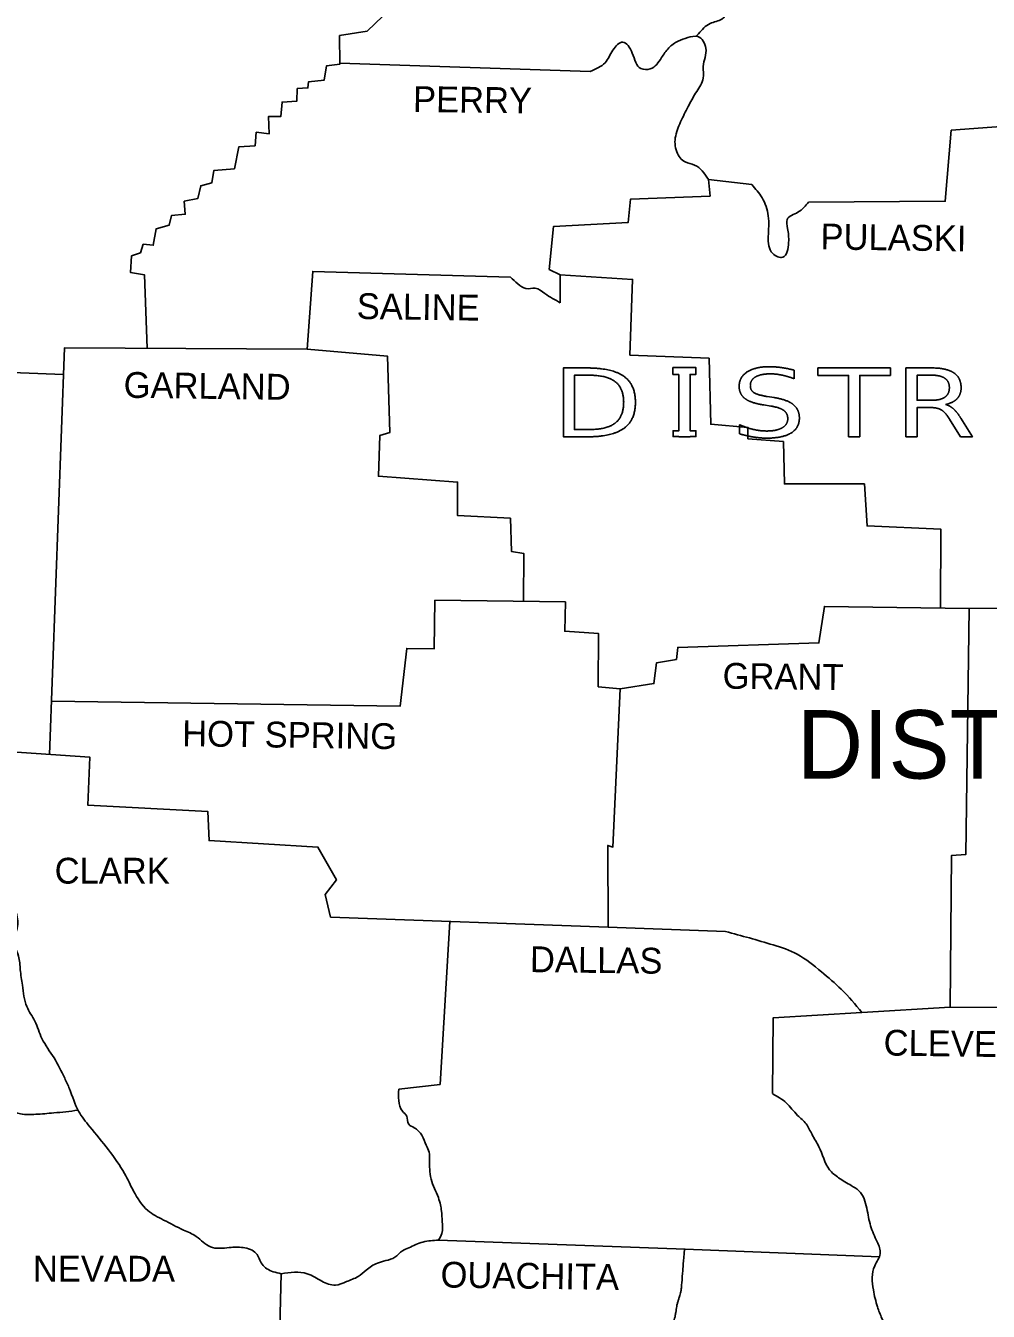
# Model space of a CAD drawing. Extents: x -0.54 to 1.64, y 0 to 0.92.
# Drawn here: x 1.1608 to 1.2333, y 0.624 to 0.7208 of the extents above; entities that cross this region are included whole.
import ezdxf

# ---------------------------------------------------------------- set-up
doc = ezdxf.new("R2010")
doc.units = 0
doc.layers.add('SHET_Annotations', color=7, linetype='Continuous')

msp = doc.modelspace()

# ---------------------------------------------------------------- linework, layer by layer
at = {"layer": 'SHET_Annotations'}
for p, q in [((1.211498, 0.720198), (1.211339, 0.720025)), ((1.218711, 0.694864), (1.218711, 0.694217)), ((1.216668, 0.692885), (1.217199, 0.692797)), ((1.216951, 0.692161), (1.216415, 0.692245)), ((1.230114, 0.69228), (1.230114, 0.69228)), ((1.214594, 0.69007), (1.214594, 0.690756))]:
    msp.add_line(p, q, dxfattribs=at)
for points in [[(1.233618, 0.817918), (1.233724, 0.806793), (1.232972, 0.806741), (1.233076, 0.795382), (1.229912, 0.794915), (1.230171, 0.79188), (1.23126, 0.790454), (1.231182, 0.786849), (1.224984, 0.786616), (1.224751, 0.781066), (1.219097, 0.780884), (1.218786, 0.77409), (1.219123, 0.773571), (1.219279, 0.762782), (1.229004, 0.762134), (1.228874, 0.738093), (1.236655, 0.737885), (1.236655, 0.713404), (1.230534, 0.712937), (1.230093, 0.707594), (1.219797, 0.707517)], [(1.188313, 0.722092), (1.18655, 0.720406), (1.184475, 0.720069), (1.184501, 0.717916), (1.183489, 0.717786), (1.183308, 0.716697), (1.182141, 0.716593), (1.182089, 0.716127), (1.181285, 0.716075), (1.181259, 0.715115), (1.180144, 0.715063), (1.180066, 0.713974), (1.179133, 0.713974), (1.179184, 0.712677), (1.178199, 0.712781), (1.178121, 0.71177), (1.176902, 0.711692), (1.176565, 0.710032), (1.175009, 0.709902), (1.174853, 0.708969), (1.174023, 0.708761), (1.173816, 0.707802), (1.172779, 0.707594), (1.172856, 0.706609), (1.171819, 0.706505), (1.171638, 0.705779), (1.170678, 0.70552), (1.170445, 0.704275), (1.169692, 0.704353), (1.169485, 0.703704), (1.168811, 0.703471), (1.168733, 0.702226), (1.169796, 0.702044), (1.169986, 0.696511)], [(1.203355, 0.717372), (1.1845, 0.717996)], [(1.215518, 0.708839), (1.21225, 0.709228), (1.21238, 0.707983), (1.206389, 0.70775), (1.206208, 0.705986), (1.20058, 0.705675), (1.200269, 0.702459), (1.201099, 0.702044), (1.201099, 0.699944)], [(1.197338, 0.701863), (1.182452, 0.702304), (1.182037, 0.696443), (1.163754, 0.696546), (1.16263, 0.665925)], [(1.201099, 0.702039), (1.206545, 0.701707), (1.206337, 0.696002), (1.212302, 0.695768), (1.212432, 0.690789), (1.215233, 0.690556), (1.215233, 0.6897), (1.217904, 0.689492), (1.217982, 0.686302), (1.223999, 0.686302), (1.224206, 0.683138), (1.229756, 0.682879), (1.22973, 0.676945)], [(1.182037, 0.696443), (1.18808, 0.695924), (1.188261, 0.690167), (1.187509, 0.689933), (1.187406, 0.686873), (1.19337, 0.686432), (1.19337, 0.683916), (1.197338, 0.683709), (1.197416, 0.681219), (1.19835, 0.681064), (1.198322, 0.677449)], [(1.145522, 0.69525), (1.16368, 0.694539)], [(1.203118, 0.695032), (1.201332, 0.695032), (1.201332, 0.689846), (1.203118, 0.689846)], [(1.203253, 0.690392), (1.202168, 0.690392), (1.202168, 0.694486), (1.203253, 0.694486)], [(1.22909, 0.695032), (1.227125, 0.695032), (1.227125, 0.689846), (1.227961, 0.689846), (1.227961, 0.692053), (1.228942, 0.692053)], [(1.22909, 0.692598), (1.227961, 0.692598), (1.227961, 0.694486), (1.22909, 0.694486)], [(1.23041, 0.691175), (1.231238, 0.689846), (1.232131, 0.689846), (1.231259, 0.691248)], [(1.284166, 0.682179), (1.266894, 0.682672), (1.26679, 0.677044), (1.231883, 0.676914)], [(1.162777, 0.66994), (1.189039, 0.669549), (1.189532, 0.673906), (1.191607, 0.67388), (1.191659, 0.677537), (1.201488, 0.677407), (1.201436, 0.675202), (1.203977, 0.675021), (1.203952, 0.671027), (1.205611, 0.670871)], [(1.205611, 0.670871), (1.208153, 0.67126), (1.208334, 0.672817), (1.209839, 0.673076), (1.209942, 0.673984), (1.220575, 0.674321), (1.22099, 0.67707), (1.231883, 0.676914)], [(1.231883, 0.676914), (1.231649, 0.658397), (1.23056, 0.658319), (1.230456, 0.646882)], [(1.205611, 0.670871), (1.205067, 0.658942), (1.204678, 0.659071), (1.204703, 0.652912)], [(1.157581, 0.657723), (1.157452, 0.660238), (1.158204, 0.66029), (1.15867, 0.666203), (1.165673, 0.665711), (1.165517, 0.662106), (1.174568, 0.661613), (1.174646, 0.659434), (1.182841, 0.658942), (1.184242, 0.656478), (1.183386, 0.655363), (1.183801, 0.653677), (1.204703, 0.652912)], [(1.192781, 0.653348), (1.192048, 0.641073), (1.188936, 0.64071)], [(1.204703, 0.652912), (1.213547, 0.652588)], [(1.230456, 0.646882), (1.223818, 0.646482)], [(1.230456, 0.646882), (1.246689, 0.646804)], [(1.223818, 0.646482), (1.217126, 0.646078), (1.217074, 0.640373)], [(1.191936, 0.629339), (1.210513, 0.628651), (1.225143, 0.628081)], [(1.180092, 0.626809), (1.179496, 0.60378), (1.173349, 0.604221), (1.173297, 0.602535), (1.165188, 0.603003)]]:
    msp.add_lwpolyline(points, dxfattribs=at)
for points in [[(1.210037, 0.694542), (1.209575, 0.694542), (1.209575, 0.69506), (1.211309, 0.69506), (1.211309, 0.694542), (1.210873, 0.694542), (1.210873, 0.690297), (1.211309, 0.690297), (1.211309, 0.68986), (1.210873, 0.68986), (1.210873, 0.689846), (1.210037, 0.689846), (1.210037, 0.68986), (1.209592, 0.68986), (1.209592, 0.690297), (1.210037, 0.690297)], [(1.220502, 0.695032), (1.225961, 0.695032), (1.225961, 0.694472), (1.223652, 0.694472), (1.223652, 0.689846), (1.222811, 0.689846), (1.222811, 0.694472), (1.220502, 0.694472)]]:
    msp.add_lwpolyline(points, close=True, dxfattribs=at)
for points in [[(1.21557, 0.732776), (1.214948, 0.731713), (1.214714, 0.730339), (1.213962, 0.729457), (1.213495, 0.728497), (1.213469, 0.727149), (1.213677, 0.725956), (1.21391, 0.724841), (1.214118, 0.723777), (1.213858, 0.722455), (1.213262, 0.721314), (1.21238, 0.720976), (1.211498, 0.720198)], [(1.203355, 0.717372), (1.20447, 0.71802), (1.205067, 0.718979), (1.205793, 0.719576), (1.206519, 0.718746), (1.207167, 0.717579), (1.207868, 0.717553), (1.208723, 0.718409), (1.209268, 0.719135), (1.209968, 0.719654), (1.210694, 0.719913), (1.211447, 0.719991), (1.212069, 0.719109), (1.211861, 0.717735), (1.211861, 0.716853), (1.211369, 0.715867), (1.210798, 0.714856), (1.210228, 0.713715), (1.209787, 0.712522), (1.209865, 0.711303), (1.210513, 0.710551), (1.211213, 0.710317), (1.21225, 0.709228)], [(1.215518, 0.708839), (1.216296, 0.707854), (1.216763, 0.706479), (1.216763, 0.704923), (1.2171, 0.703652), (1.217852, 0.703367), (1.218293, 0.704482), (1.218215, 0.705546), (1.218189, 0.70622), (1.218993, 0.706764), (1.219797, 0.707517)], [(1.201099, 0.699944), (1.199932, 0.700644), (1.199206, 0.701033), (1.198505, 0.701007), (1.197909, 0.70137), (1.197338, 0.701863)], [(1.157581, 0.657723), (1.158281, 0.657282), (1.159163, 0.656867), (1.15963, 0.656193), (1.159786, 0.655129), (1.160123, 0.653988), (1.160201, 0.652821), (1.159941, 0.652173), (1.160304, 0.650721), (1.160434, 0.649709), (1.16059, 0.648542), (1.160927, 0.646934), (1.161523, 0.645845), (1.162068, 0.644522), (1.162976, 0.64307), (1.163779, 0.64154), (1.164143, 0.640736), (1.164817, 0.63905), (1.165673, 0.637883), (1.167073, 0.636146), (1.168292, 0.634356), (1.168966, 0.633033), (1.17003, 0.631581), (1.171223, 0.630855), (1.172727, 0.630103), (1.173686, 0.62961), (1.17475, 0.628832), (1.176176, 0.62878), (1.177213, 0.62878), (1.178199, 0.628339), (1.17864, 0.627535), (1.17947, 0.626965), (1.180092, 0.626809)], [(1.213547, 0.652588), (1.217126, 0.651576), (1.218942, 0.650876), (1.220757, 0.649554), (1.222261, 0.648231), (1.223818, 0.646482)], [(1.138891, 0.642598), (1.140802, 0.642448), (1.14241, 0.642266), (1.143629, 0.642136), (1.144899, 0.641696), (1.146066, 0.641281), (1.146793, 0.640943), (1.148011, 0.641021), (1.149075, 0.640814), (1.150242, 0.640399), (1.151124, 0.639621), (1.151694, 0.639024), (1.152731, 0.638791), (1.153613, 0.638946), (1.154651, 0.638843), (1.155818, 0.638506), (1.156803, 0.638532), (1.157581, 0.638713), (1.158489, 0.638921), (1.159604, 0.63905), (1.16046, 0.638843), (1.161601, 0.638817), (1.16295, 0.638921), (1.164779, 0.63912)], [(1.188936, 0.64071), (1.188936, 0.639854), (1.189221, 0.63905), (1.189532, 0.638687), (1.189688, 0.638065), (1.190103, 0.637805), (1.190673, 0.637235), (1.19101, 0.636483), (1.191218, 0.635964), (1.191244, 0.635316), (1.19127, 0.634693), (1.191373, 0.633941), (1.191918, 0.632541), (1.192074, 0.631996), (1.192151, 0.631529), (1.192203, 0.630751), (1.192177, 0.629844), (1.191936, 0.629339)], [(1.217074, 0.640373), (1.218112, 0.639673), (1.218967, 0.638739), (1.219616, 0.638091), (1.220057, 0.637287), (1.220575, 0.636379), (1.221379, 0.634641), (1.222054, 0.634045), (1.223013, 0.633448), (1.223584, 0.633059), (1.22418, 0.631737), (1.224466, 0.630414), (1.224958, 0.629221), (1.225192, 0.628313), (1.224777, 0.627406), (1.224673, 0.62559), (1.224984, 0.62432), (1.225321, 0.623438), (1.225555, 0.622375), (1.225399, 0.622063)], [(1.189687, 0.628755), (1.189221, 0.628547), (1.18865, 0.628054), (1.18795, 0.627795), (1.187328, 0.627613), (1.186472, 0.627069), (1.185875, 0.626602), (1.184994, 0.626213), (1.184164, 0.625953), (1.183152, 0.626239), (1.182608, 0.62655), (1.182037, 0.626809), (1.180092, 0.626809)], [(1.189687, 0.628755), (1.190751, 0.629195), (1.191936, 0.629339)]]:
    msp.add_spline(points, degree=3, dxfattribs=at)
for points, degree in [([(1.205878, 0.694406), (1.205, 0.695032), (1.203118, 0.695032)], 2), ([(1.203253, 0.694486), (1.204608, 0.694486), (1.205239, 0.693995)], 2), ([(1.206756, 0.692444), (1.206756, 0.69378), (1.205878, 0.694406)], 2), ([(1.214568, 0.693654), (1.214568, 0.694336), (1.215169, 0.694731)], 2), ([(1.215169, 0.694731), (1.215771, 0.695126), (1.216829, 0.695126)], 2), ([(1.215805, 0.69436), (1.215409, 0.694133), (1.215409, 0.69371)], 2), ([(1.216929, 0.694588), (1.216202, 0.694588), (1.215805, 0.69436)], 2), ([(1.216829, 0.695126), (1.217287, 0.695126), (1.217759, 0.69506)], 2), ([(1.217792, 0.694493), (1.217343, 0.694588), (1.216929, 0.694588)], 2), ([(1.217759, 0.69506), (1.218232, 0.694993), (1.218711, 0.694864)], 2), ([(1.218711, 0.694217), (1.218241, 0.694399), (1.217792, 0.694493)], 2), ([(1.230739, 0.694661), (1.230196, 0.695032), (1.22909, 0.695032)], 2), ([(1.22909, 0.694486), (1.229734, 0.694486), (1.230066, 0.694249)], 2), ([(1.231281, 0.693546), (1.231281, 0.69429), (1.230739, 0.694661)], 2), ([(1.205239, 0.693995), (1.205871, 0.693504), (1.205871, 0.692444)], 2), ([(1.215002, 0.692731), (1.214568, 0.693063), (1.214568, 0.693654)], 2), ([(1.215409, 0.69371), (1.215409, 0.693353), (1.215675, 0.693175)], 2), ([(1.230066, 0.694249), (1.230397, 0.694011), (1.230397, 0.693546)], 2), ([(1.230397, 0.693546), (1.230397, 0.693081), (1.230066, 0.692839)], 2), ([(1.231, 0.69274), (1.231281, 0.69306), (1.231281, 0.693546)], 2), ([(1.205871, 0.692444), (1.205871, 0.691378), (1.205239, 0.690885)], 2), ([(1.205875, 0.690474), (1.206756, 0.691102), (1.206756, 0.692444)], 2), ([(1.216415, 0.692245), (1.215435, 0.692399), (1.215002, 0.692731)], 2), ([(1.215675, 0.693175), (1.21594, 0.692997), (1.216668, 0.692885)], 2), ([(1.217199, 0.692797), (1.21818, 0.692651), (1.218641, 0.692275)], 2), ([(1.230066, 0.692839), (1.229734, 0.692598), (1.22909, 0.692598)], 2), ([(1.230114, 0.69228), (1.230719, 0.69242), (1.231, 0.69274)], 2), ([(1.217929, 0.691831), (1.217631, 0.692053), (1.216951, 0.692161)], 2), ([(1.218228, 0.691217), (1.218228, 0.691609), (1.217929, 0.691831)], 2), ([(1.218641, 0.692275), (1.219103, 0.691899), (1.219103, 0.691269)], 2), ([(1.228942, 0.692053), (1.229473, 0.692053), (1.22978, 0.69188)], 2), ([(1.22978, 0.69188), (1.230087, 0.691707), (1.23041, 0.691175)], 2), ([(1.230723, 0.691936), (1.230458, 0.692186), (1.230114, 0.69228)], 2), ([(1.231259, 0.691248), (1.230989, 0.691686), (1.230723, 0.691936)], 2), ([(1.203118, 0.689846), (1.204995, 0.689846), (1.205875, 0.690474)], 2), ([(1.205239, 0.690885), (1.204608, 0.690392), (1.203253, 0.690392)], 2), ([(1.214594, 0.690756), (1.2151, 0.690532), (1.215616, 0.690408)], 2), ([(1.215616, 0.690408), (1.216132, 0.690283), (1.216633, 0.690283)], 2), ([(1.216633, 0.690283), (1.217395, 0.690283), (1.217812, 0.690525)], 2), ([(1.217812, 0.690525), (1.218228, 0.690766), (1.218228, 0.691217)], 2), ([(1.219103, 0.691269), (1.219103, 0.690518), (1.218476, 0.690131)], 2), ([(1.215655, 0.689829), (1.215139, 0.689913), (1.214594, 0.69007)], 2), ([(1.216633, 0.689745), (1.216171, 0.689745), (1.215655, 0.689829)], 2), ([(1.218476, 0.690131), (1.217849, 0.689745), (1.216633, 0.689745)], 2), ([(1.210451, 0.628653), (1.210376, 0.627719), (1.210302, 0.626784), (1.210228, 0.62585), (1.210209, 0.625611), (1.210151, 0.625376), (1.210087, 0.625145), (1.210054, 0.625029), (1.210018, 0.624914), (1.209985, 0.624798), (1.209952, 0.624682), (1.209919, 0.624566), (1.20989, 0.624449), (1.209838, 0.624232), (1.209823, 0.624009), (1.209781, 0.62379), (1.20976, 0.62368), (1.209738, 0.623572), (1.209709, 0.623464), (1.209694, 0.62341), (1.209675, 0.623358), (1.209653, 0.623306), (1.209643, 0.62328), (1.209631, 0.623254), (1.209619, 0.623229), (1.209607, 0.623203), (1.209594, 0.623177), (1.209579, 0.623153), (1.209537, 0.623078), (1.209488, 0.623009), (1.209431, 0.622945), (1.209374, 0.622882), (1.209315, 0.622822), (1.209253, 0.622766), (1.20919, 0.62271), (1.209125, 0.622656), (1.209063, 0.622599), (1.209001, 0.622542), (1.208937, 0.622487), (1.208879, 0.622426), (1.208758, 0.622301), (1.208637, 0.622176), (1.208516, 0.62205), (1.208395, 0.621925), (1.208274, 0.6218), (1.208153, 0.621674), (1.207914, 0.621427), (1.207707, 0.62115), (1.207505, 0.62087), (1.207448, 0.620791), (1.207392, 0.620712), (1.207342, 0.620629), (1.207292, 0.620545), (1.207243, 0.620462), (1.207193, 0.620378), (1.207143, 0.620295), (1.207094, 0.620211), (1.207044, 0.620128), (1.206994, 0.620044), (1.206939, 0.619964), (1.206882, 0.619885), (1.206706, 0.61964), (1.206501, 0.619424), (1.206286, 0.619211), (1.206052, 0.618979), (1.205814, 0.618756), (1.205534, 0.618588), (1.20527, 0.61843), (1.205001, 0.618288), (1.20473, 0.618147), (1.204455, 0.618005), (1.204181, 0.617863), (1.2039, 0.617732), (1.203823, 0.617697), (1.203744, 0.617667), (1.203662, 0.617647), (1.203579, 0.617627), (1.203497, 0.61761), (1.203414, 0.617593), (1.20333, 0.617576), (1.203246, 0.617561), (1.203162, 0.617543), (1.203078, 0.617526), (1.202996, 0.617501), (1.202914, 0.617473), (1.202784, 0.617429), (1.202661, 0.617369), (1.202544, 0.617295), (1.202485, 0.617258), (1.202432, 0.617216), (1.202381, 0.617169), (1.202356, 0.617144), (1.202331, 0.617119), (1.202308, 0.617092), (1.202283, 0.617065), (1.202261, 0.617037), (1.20224, 0.617006), (1.202183, 0.616924), (1.202146, 0.616835), (1.202116, 0.616739), (1.202087, 0.616644), (1.202076, 0.616546), (1.202085, 0.61645), (1.202103, 0.616262), (1.202136, 0.616071), (1.202214, 0.615891), (1.202271, 0.615759), (1.202329, 0.615633), (1.202395, 0.615509), (1.202461, 0.615382), (1.202528, 0.615257), (1.202594, 0.61513), (1.20266, 0.615004), (1.202726, 0.614877), (1.202791, 0.61475), (1.202856, 0.614623), (1.202913, 0.614493), (1.202966, 0.614361), (1.203061, 0.614122), (1.203145, 0.613879), (1.203225, 0.613635), (1.20325, 0.613561), (1.203272, 0.613487), (1.203293, 0.613412), (1.203314, 0.613336), (1.203331, 0.61326), (1.203345, 0.613182), (1.203359, 0.613106), (1.203367, 0.613029), (1.20337, 0.612952), (1.203372, 0.612914), (1.20337, 0.612877), (1.203368, 0.612839), (1.203367, 0.612801), (1.203362, 0.612764), (1.203355, 0.612727), (1.203336, 0.612626), (1.203291, 0.612534), (1.203226, 0.61245), (1.203157, 0.612362), (1.203082, 0.612291), (1.202992, 0.612234), (1.202761, 0.612089), (1.20253, 0.61195), (1.202292, 0.611819), (1.202, 0.611659), (1.201701, 0.611514), (1.20141, 0.611352), (1.201147, 0.611207), (1.2009, 0.611042), (1.200658, 0.61086), (1.20053, 0.610764), (1.200421, 0.610651), (1.200322, 0.610526), (1.200273, 0.610462), (1.200231, 0.610397), (1.200192, 0.610327), (1.200152, 0.610256), (1.200118, 0.610185), (1.200087, 0.610108), (1.20002, 0.609933), (1.199976, 0.609755), (1.199966, 0.609575), (1.199956, 0.609399), (1.199967, 0.609217), (1.20001, 0.609044), (1.200035, 0.608942), (1.20006, 0.60884), (1.200089, 0.608739), (1.200119, 0.608638), (1.200148, 0.608537), (1.200178, 0.608435), (1.200208, 0.608334), (1.200237, 0.608232), (1.200267, 0.608131), (1.200296, 0.60803), (1.200323, 0.607928), (1.200347, 0.607825), (1.200405, 0.607576), (1.200448, 0.607324), (1.200502, 0.607073), (1.200526, 0.606966), (1.200552, 0.606859), (1.200578, 0.606753), (1.200604, 0.606644), (1.20064, 0.606539), (1.200679, 0.606434), (1.200718, 0.606333), (1.200773, 0.606242), (1.200842, 0.606157), (1.200876, 0.606114), (1.200914, 0.606078), (1.200956, 0.606045), (1.200978, 0.606028), (1.201, 0.606013), (1.201024, 0.605998), (1.201048, 0.605983), (1.201072, 0.60597), (1.201099, 0.605958), (1.201135, 0.605943), (1.201172, 0.605933), (1.201209, 0.605934), (1.201246, 0.605934), (1.201283, 0.605939), (1.201319, 0.605946), (1.201356, 0.605953), (1.201392, 0.605965), (1.201429, 0.605971), (1.201466, 0.605976), (1.201503, 0.605981), (1.20154, 0.605984), (1.201574, 0.605987), (1.201609, 0.605986), (1.201643, 0.605991), (1.201678, 0.605996), (1.201713, 0.606002), (1.201747, 0.606007), (1.201817, 0.606019), (1.201886, 0.606031), (1.201955, 0.606043), (1.202023, 0.606054), (1.202094, 0.606049), (1.202162, 0.606036), (1.202199, 0.606028), (1.202233, 0.606016), (1.202266, 0.605999), (1.202284, 0.60599), (1.202301, 0.60598), (1.202318, 0.60597), (1.202336, 0.605959), (1.202353, 0.605948), (1.20237, 0.605932), (1.202402, 0.605902), (1.202422, 0.605862), (1.202431, 0.60582), (1.20244, 0.60578), (1.202438, 0.605739), (1.202447, 0.605699), (1.202463, 0.605629), (1.20248, 0.60556), (1.202499, 0.605491), (1.202555, 0.605288), (1.202618, 0.60509), (1.202707, 0.604895), (1.202735, 0.604832), (1.202782, 0.604775), (1.202842, 0.604745), (1.202909, 0.604712), (1.202976, 0.60468), (1.203043, 0.604647), (1.20311, 0.604615), (1.203177, 0.604583), (1.203244, 0.60455), (1.203305, 0.604521), (1.203352, 0.604465), (1.203381, 0.604402), (1.203398, 0.604365), (1.203409, 0.604328), (1.203416, 0.604289), (1.203423, 0.604249), (1.203429, 0.60421), (1.203435, 0.60417), (1.203442, 0.60413), (1.203447, 0.60409), (1.203454, 0.60405), (1.20346, 0.604011), (1.203472, 0.603973), (1.203485, 0.603935), (1.203536, 0.603782), (1.203599, 0.603635), (1.203665, 0.603486), (1.203731, 0.603335), (1.203807, 0.603194), (1.2039, 0.603054), (1.204065, 0.602803), (1.204274, 0.602572), (1.204548, 0.602457), (1.204719, 0.602385), (1.204891, 0.602329), (1.205067, 0.602276), (1.205412, 0.60217), (1.205757, 0.602064), (1.206104, 0.601964), (1.206283, 0.601913), (1.206468, 0.601882), (1.206649, 0.601835), (1.206677, 0.601827), (1.206703, 0.601817), (1.206727, 0.601799), (1.206804, 0.601742), (1.206859, 0.601665), (1.206876, 0.601578), (1.206904, 0.601432), (1.206928, 0.601285), (1.206956, 0.601139), (1.206983, 0.600998), (1.207009, 0.600858), (1.207038, 0.600717), (1.207049, 0.600662), (1.20708, 0.600616), (1.207126, 0.600575), (1.207171, 0.600536), (1.207219, 0.600516), (1.207271, 0.600512), (1.207392, 0.600503), (1.207514, 0.600503), (1.207634, 0.600516), (1.207755, 0.60053), (1.207877, 0.60054), (1.207997, 0.600564), (1.208084, 0.600581), (1.20817, 0.600601), (1.208257, 0.600618), (1.208343, 0.600636), (1.208429, 0.600652), (1.208516, 0.600668), (1.20867, 0.600695), (1.208832, 0.600683), (1.208987, 0.600651), (1.209068, 0.600634), (1.209145, 0.600608), (1.20922, 0.600573), (1.20926, 0.600554), (1.209298, 0.600534), (1.209335, 0.600512), (1.209375, 0.600488), (1.209413, 0.600463), (1.20945, 0.600434), (1.209541, 0.600361), (1.209623, 0.600276), (1.209683, 0.600176), (1.209738, 0.600082), (1.20979, 0.599987), (1.209839, 0.59989), (1.209877, 0.599813), (1.209919, 0.599737), (1.209954, 0.599658), (1.209988, 0.59958), (1.210023, 0.599501), (1.210057, 0.599423), (1.210092, 0.599344), (1.210127, 0.599266), (1.210162, 0.599188), (1.210197, 0.599109), (1.210239, 0.599033), (1.210279, 0.598956), (1.210366, 0.598792), (1.210441, 0.598617), (1.210564, 0.598478)], 3)]:
    msp.add_open_spline(points, degree=degree, dxfattribs=at)

# ---------------------------------------------------------------- texts
for s, rotation, p in [('PERRY', 359.29917, (1.189999, 0.714314)), ('PULASKI', 359.18542, (1.220683, 0.703965)), ('SALINE', 359.1885, (1.185762, 0.698726)), ('GARLAND', 359.2717, (1.168207, 0.692788)), ('GRANT', 359.31386, (1.213312, 0.670879)), ('HOT SPRING', 359.19559, (1.172613, 0.666543)), ('DALLAS', 359.28024, (1.198804, 0.649529)), ('CLEVELAND', 359.24116, (1.225436, 0.643246)), ('OUACHITA', 359.20269, (1.192074, 0.625774))]:
    msp.add_text(s, height=0.0019451, rotation=rotation, dxfattribs=at).set_placement(p)
for s, height, p in [('DISTRICT 2', 0.0051569, (1.218919, 0.664104)), ('CLARK', 0.0019451, (1.163021, 0.656193)), ('NEVADA', 0.0019451, (1.161389, 0.626213))]:
    msp.add_text(s, height=height, dxfattribs=at).set_placement(p)

doc.saveas('drawing.dxf')
